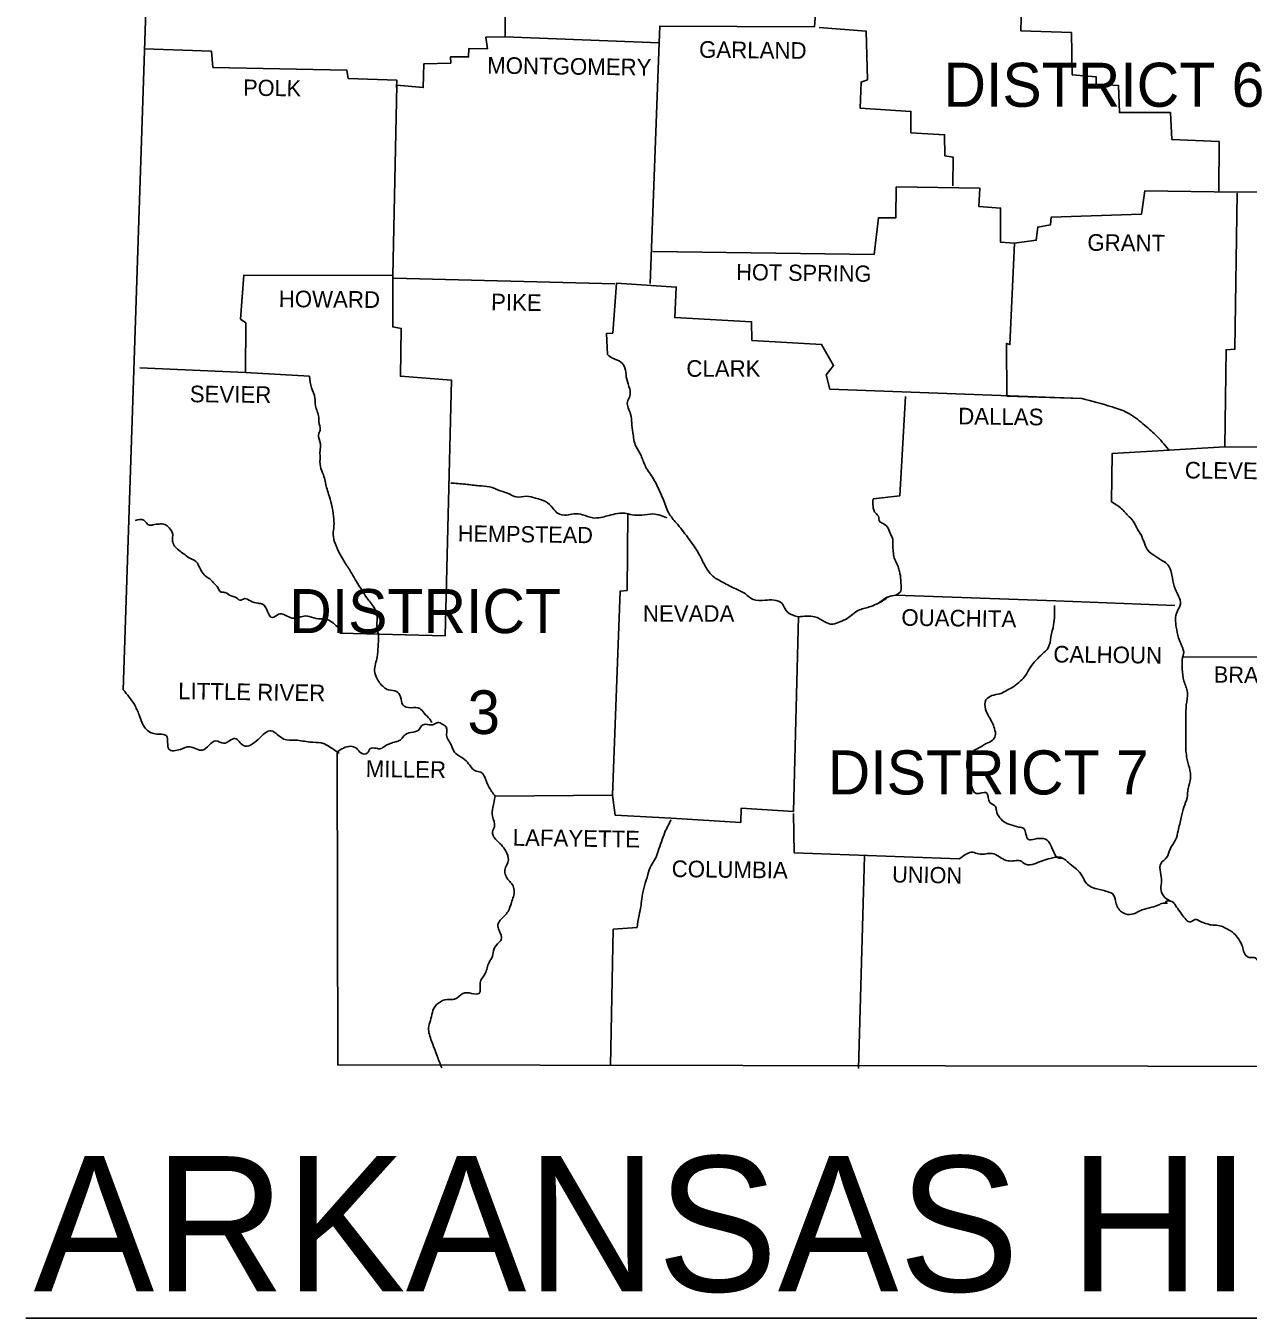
# Model space of a CAD drawing. Extents: x -33639 to 34530, y -17264 to 5867.
# Drawn here: x 1258 to 2998, y 2539 to 4379 of the extents above; entities that cross this region are included whole.
import ezdxf

# ---------------------------------------------------------------- set-up
doc = ezdxf.new("R2010")
doc.units = 0
for name, color, linetype in [('1', 7, 'Continuous'), ('2', 7, 'Continuous'), ('3', 7, 'Continuous'), ('S_MISC_BOUNDARY', 7, 'Continuous')]:
    doc.layers.add(name, color=color, linetype=linetype)

msp = doc.modelspace()

# ---------------------------------------------------------------- linework, layer by layer
at = {"layer": '1'}
msp.add_line((1258, 2539.3), (4771.1, 2539.3), dxfattribs=at)
for points in [[(1332.2, 5841.4), (1446.1, 4926.7), (1396.6, 3433.6)], [(1941.4, 4685.1), (1940.3, 4363.2), (1912.8, 4362.6), (1915, 4346.1), (1888.6, 4346.7), (1888, 4334.6), (1862.2, 4334.6), (1862.7, 4325.8), (1824.2, 4324.7), (1823.6, 4291.1), (1786.2, 4294.4), (1780.2, 4023.6), (1568.3, 4024.2), (1563.3, 3961.4), (1571, 3955.9), (1570.5, 3885.5), (1420.2, 3892.1)], [(2565.5, 4443), (2385.5, 4448.5), (2380.6, 4377.5), (2160.4, 4378.6), (2159.3, 4354.9)], [(2614.5, 4444.6), (2676.1, 4440.8), (2673.9, 4372), (2746, 4369.2), (2747.1, 4309.2), (2781.2, 4306.5), (2781.2, 4296), (2813.2, 4293.8), (2814.3, 4255.3), (2886.9, 4255.3), (2889.1, 4217.3), (2956.3, 4214), (2955.7, 4142.5)], [(2159.3, 4354.9), (1940.3, 4363.2)], [(2387.2, 4376.4), (2453.8, 4371.4), (2456, 4302.1), (2446.6, 4298.8), (2445.5, 4261.9), (2517.6, 4257), (2517.6, 4226.7), (2565.5, 4223.9), (2566.1, 4193.7), (2577.6, 4192), (2577.1, 4151.3)], [(1426.8, 4346.1), (1522, 4342.8), (1524.2, 4319.7), (1714.7, 4315.8), (1716.9, 4303.7), (1786.2, 4301.5), (1785.7, 4291.1)], [(2159.3, 4354.9), (2146.7, 4012.1)], [(2150.5, 4057.7), (2465.3, 4053.3), (2471.4, 4105.6), (2496.2, 4105.6), (2496.7, 4149.6), (2615.6, 4148), (2614.5, 4121.6), (2645.3, 4119.4), (2645.3, 4070.9), (2665.1, 4069.3)], [(2982.1, 4140.8), (2978.8, 3918.5), (2966.2, 3917.9), (2964.5, 3779.8)], [(1780.2, 4023.6), (1780.2, 3950.4), (1792.3, 3948.2), (1791.2, 3880), (1863.8, 3874.5), (1855, 3510.7), (1705.3, 3514.5)], [(1781.3, 4019.8), (2096.1, 4011.5)], [(2085.6, 3910.8), (2084.5, 3941.1), (2093.3, 3941.6), (2098.8, 4012.6), (2183.6, 4007.1), (2181.4, 3963.6), (2290.9, 3957.6), (2291.4, 3931.2), (2390.5, 3925.1), (2407.6, 3895.4), (2397.1, 3882.2), (2402.1, 3861.8), (2760.9, 3848.6)], [(1570.5, 3885.5), (1661.8, 3880)], [(2509.9, 3851.4), (2501.7, 3709.9), (2463.7, 3705.5)], [(2885.3, 3774.9), (2803.8, 3769.9), (2803.3, 3701.1)], [(2114.8, 3684.6), (2113.7, 3575.1), (2103.8, 3574), (2092.8, 3283.9)], [(2496.2, 3568.5), (2724, 3560.2), (2893, 3553.6)], [(2357.5, 3537.6), (2350.3, 3260.3), (2276, 3265.2), (2275.5, 3244.9), (2176.4, 3250.9)], [(2904, 3480.4), (3152.7, 3481)], [(1700.9, 3345), (1702, 2899.8), (3719, 2896.5)], [(2176.4, 3250.9), (2096.6, 3255.3), (2092.8, 3283.9), (1926, 3282.3)], [(2586.4, 3193.1), (2351.4, 3201.9), (2350.3, 3257.5)], [(2451.6, 3197), (2442.8, 2894.8)], [(2128, 3095.2), (2093.9, 3093), (2090, 2899.2)]]:
    msp.add_lwpolyline(points, dxfattribs=at)
for points in [[(2085.6, 3910.8), (2094.4, 3905.3), (2104.9, 3900.3), (2110.4, 3892.1), (2112.6, 3879.4), (2116.4, 3865.7), (2117.5, 3851.4), (2114.2, 3843.6), (2118.6, 3826), (2120.3, 3813.9), (2121.9, 3799.6), (2126.3, 3780.4), (2133.5, 3767.1), (2140.1, 3751.2), (2151.1, 3734.1), (2160.4, 3715.4), (2164.8, 3705.5), (2173.1, 3685.1), (2183.6, 3671.4), (2200.1, 3650.5), (2214.9, 3629), (2223.2, 3613), (2235.8, 3595.4), (2250.2, 3586.6), (2268.3, 3577.3), (2279.9, 3571.8), (2293.1, 3562.4), (2310.1, 3561.3), (2322.8, 3561.3), (2334.4, 3556.4), (2339.9, 3546.5), (2349.8, 3539.9), (2357.5, 3537.6)], [(1661.8, 3880), (1664.6, 3863.5), (1669.5, 3849.1), (1670.1, 3838.1), (1675, 3821.6), (1675, 3815.6), (1676.7, 3803.5), (1674.5, 3796.9), (1677.2, 3783.7), (1676.7, 3773.8), (1676.7, 3765.5), (1677.2, 3751.7), (1681.6, 3739.6), (1686, 3721.5), (1688.8, 3712.1), (1693.2, 3697.8), (1695.9, 3680.2), (1696.5, 3667), (1695.4, 3654.9), (1698.7, 3641.1), (1704.8, 3627.4), (1712.5, 3614.1), (1721.8, 3599.3), (1728.4, 3587.7), (1736.7, 3575.1), (1743.3, 3564.6), (1753.2, 3551.4), (1757.6, 3540.4), (1757.6, 3525), (1759.8, 3510.7), (1759.2, 3494.7), (1758.1, 3480.4), (1754.3, 3460.6), (1757, 3451.2), (1767.5, 3437.5), (1774.1, 3433.6), (1785.7, 3431.4), (1791.2, 3423.7), (1794.5, 3412.2), (1806, 3408.3), (1818.7, 3407.2), (1824.7, 3400.6), (1833, 3391.8), (1835.7, 3387.4)], [(1862.7, 3728.1), (1883.6, 3726.4), (1902.9, 3724.2), (1917.7, 3722.6), (1933.2, 3717.1), (1946.9, 3712.1), (1955.7, 3708.3), (1970.6, 3709.4), (1983.2, 3706.6), (1997.5, 3701.7), (2008, 3692.3), (2014.6, 3685.1), (2027.3, 3682.4), (2037.7, 3684), (2050.4, 3682.9), (2064.7, 3678.5), (2076.2, 3679.1), (2085.6, 3681.3), (2096.6, 3684), (2110.4, 3685.1), (2120.8, 3682.9), (2134.6, 3682.4), (2150.5, 3684), (2170.4, 3678.5)], [(2463.7, 3705.5), (2463.7, 3695), (2467.5, 3685.1), (2471.4, 3680.7), (2473, 3673.6), (2478, 3670.3), (2485.2, 3663.7), (2489, 3654.3), (2491.8, 3648.3), (2491.8, 3640.6), (2492.3, 3632.9), (2493.4, 3623.5), (2500, 3607), (2501.7, 3600.4), (2502.8, 3594.9), (2503.3, 3585.5), (2503.3, 3574.5), (2496.2, 3568.5)], [(2803.3, 3701.1), (2815.9, 3692.8), (2826.4, 3681.8), (2834.1, 3673.6), (2839, 3664.2), (2845.6, 3653.2), (2855, 3632.3), (2863.2, 3625.2), (2874.8, 3618), (2882, 3613), (2889.1, 3597.1), (2892.4, 3581.1), (2898.5, 3566.8), (2901.2, 3555.8), (2896.3, 3544.8), (2895.2, 3522.8), (2898.5, 3507.9), (2902.9, 3496.9), (2905.6, 3484.3), (2904, 3480.4)], [(1413.6, 3674.7), (1425.7, 3675.2), (1434, 3668.1), (1438.9, 3668.6), (1447.7, 3669.7), (1456, 3669.2), (1462, 3664.2), (1467, 3655.4), (1466.5, 3647.2), (1467, 3643.9), (1470.9, 3636.7), (1477.5, 3631.2), (1484.6, 3625.7), (1491.2, 3621.3), (1502.2, 3614.1), (1503.3, 3611.9), (1507.7, 3603.1), (1513.2, 3596), (1519.8, 3591.6), (1527, 3583.9), (1530.3, 3580.6), (1535.8, 3572.9), (1541.8, 3572.3), (1550.1, 3567.4), (1556.2, 3565.7), (1562.8, 3561.3), (1569.4, 3563.5), (1577.6, 3560.2), (1588.6, 3556.9), (1594.7, 3555.8), (1601.8, 3545.4), (1609, 3536.5), (1617.8, 3541.5), (1634.3, 3536.5), (1644.8, 3536), (1654.1, 3538.7), (1661.3, 3538.2), (1674.5, 3534.9), (1682.7, 3534.9), (1691.5, 3531.6), (1699.8, 3525), (1705.3, 3517.8), (1705.3, 3514.5)], [(2485.7, 3566.3), (2471.4, 3556.9), (2460.4, 3552.5), (2452.1, 3549.8), (2444.4, 3547.6), (2434.5, 3541), (2426.8, 3535.4), (2416.4, 3530.5), (2406.5, 3527.2), (2394.3, 3531), (2387.7, 3534.9), (2380.6, 3537.6), (2357.5, 3537.6)], [(2471.4, 3556.9), (2485.7, 3566.3), (2496.2, 3568.5)], [(2721.8, 3553.6), (2720.7, 3526.1), (2716.9, 3509), (2713, 3493.6), (2704.7, 3484.8), (2695.9, 3476), (2687.7, 3466.1), (2680.5, 3454), (2673.4, 3446.3), (2664, 3438.6), (2654.7, 3433.1), (2644.2, 3428.1), (2632.7, 3425.4), (2624.4, 3419.3), (2623.8, 3406.1), (2633.2, 3387.4), (2636.5, 3378.6), (2637.6, 3368.1), (2633.8, 3362.1), (2624.9, 3357.1), (2614.5, 3351.1), (2605.1, 3345.6), (2598.5, 3336.2), (2597.4, 3323.6), (2601.8, 3308.7), (2603.5, 3299.9), (2610.6, 3286.1), (2616.1, 3286.7), (2626, 3286.1), (2627.1, 3283.4), (2627.7, 3280.6), (2629.9, 3273.5), (2638.2, 3267.4), (2639.3, 3261.9), (2644.2, 3251.5), (2652.5, 3244.3), (2658.5, 3242.1), (2671.2, 3238.3), (2677.8, 3236.6), (2684.9, 3220.6), (2693.7, 3221.2), (2700.3, 3222.3), (2711.4, 3219.5), (2716.3, 3212.9), (2721.3, 3201.9), (2727.9, 3194.2), (2732.3, 3194.2)], [(2904, 3480.4), (2906.2, 3446.3), (2911.1, 3429.8), (2909.5, 3412.2), (2908.9, 3395.1), (2908.9, 3379.7), (2908.9, 3364.8), (2908.9, 3349.4), (2910, 3338.4), (2913.9, 3322.5), (2915.5, 3307.6), (2912.2, 3293.3), (2910.6, 3280.1), (2906.2, 3266.9), (2902.3, 3252), (2897.9, 3232.8), (2894.1, 3220.1), (2886.4, 3206.9), (2881.4, 3194.8), (2873.7, 3187.1), (2872.6, 3173.9), (2874.3, 3161.8), (2873.2, 3150.7), (2877, 3140.3), (2886.9, 3133.1)], [(1396.6, 3433.6), (1412.5, 3412.7), (1419.1, 3397.9), (1428.5, 3378.6), (1442.2, 3370.9), (1458.2, 3368.1), (1461.5, 3349.4), (1478, 3348.9), (1491.2, 3352.7), (1509.4, 3347.8), (1528.6, 3361), (1539.6, 3357.7), (1555.6, 3364.3), (1567.7, 3354.4), (1588.6, 3363.2), (1607.3, 3375.3), (1625, 3363.7), (1642, 3362.1), (1662.4, 3359.3), (1678.3, 3358.2), (1692.6, 3351.1), (1703.1, 3343.9), (1700.9, 3345)], [(1700.9, 3345), (1720.2, 3353.3), (1728.4, 3350.5), (1735.6, 3343.4), (1743.8, 3343.4), (1748.2, 3350), (1756.5, 3350.5), (1763.1, 3350), (1770.2, 3354.4), (1776.3, 3357.1), (1784.6, 3359.9), (1790.6, 3362.1), (1796.1, 3368.1), (1806, 3373.1), (1817.6, 3376.9), (1820.9, 3382.4), (1826.4, 3384.7), (1837.4, 3384.1), (1844.5, 3387.4), (1850.6, 3384.7), (1856.1, 3380.8), (1857.2, 3366.5), (1861.6, 3358.8), (1868.2, 3345), (1877.6, 3337.9), (1886.4, 3330.7), (1889.7, 3326.3), (1899, 3318.1), (1907.3, 3315.3), (1911.1, 3309.3), (1917.2, 3294.9), (1926, 3282.3)], [(1926, 3282.3), (1922.7, 3266.3), (1922.1, 3253.7), (1924.9, 3238.8), (1922.1, 3231.7), (1926.5, 3221.2), (1934.8, 3212.9), (1940.9, 3204.1), (1944.7, 3191.5), (1939.8, 3177.2), (1945.3, 3162.3), (1950.2, 3156.8), (1953, 3148), (1949.1, 3130.9), (1944.2, 3118.3), (1933.2, 3105.6), (1929.8, 3099.6), (1931.5, 3091.3), (1934.3, 3078.1), (1931.5, 3074.3), (1924.3, 3064.9), (1922.1, 3054.4), (1917.2, 3045.6), (1911.7, 3029.7), (1904.5, 3016.5), (1903.4, 3001.6), (1892.4, 3001.6), (1879.8, 3001.6), (1868.2, 2993.3), (1857.8, 2992.8), (1845.1, 2987.8), (1837.4, 2977.4), (1834.6, 2965.8), (1831.3, 2954.8), (1834.6, 2936.1), (1839.6, 2922.9), (1843.4, 2912.4), (1850, 2895.4)], [(2128, 3095.2), (2130.7, 3112.8), (2133.5, 3126.5), (2135.1, 3139.7), (2138.4, 3154.6), (2143.4, 3170.6), (2147.8, 3183.8), (2153.8, 3193.1), (2157.7, 3204.1), (2162.6, 3217.3), (2167.6, 3231.1), (2176.4, 3248.7)], [(2586.4, 3193.1), (2595.2, 3199.2), (2603.5, 3202.5), (2611.7, 3200.8), (2620.5, 3199.7), (2628.2, 3200.8), (2638.2, 3199.2), (2646.4, 3194.2), (2655.8, 3190.4), (2665.1, 3190.4), (2673.4, 3190.4), (2680.5, 3185.4), (2693.7, 3186), (2704.7, 3190.4), (2715.8, 3193.7), (2730.6, 3195.3), (2743.8, 3186), (2753.2, 3178.3), (2760.9, 3169.5), (2766.4, 3159.6), (2772.4, 3154.1), (2782.3, 3150.2), (2790.1, 3148.5), (2799.4, 3145.8), (2804.4, 3143.6), (2808.8, 3133.1), (2815.9, 3118.8), (2829.7, 3113.9), (2846.7, 3120.5), (2860.5, 3124.3), (2870.4, 3127.6), (2876.5, 3129.8), (2882, 3130.4), (2880.3, 3131.5), (2886.9, 3133.1), (2893, 3128.7), (2896.8, 3122.7), (2903.4, 3113.9), (2909.5, 3106.2), (2915.5, 3103.4), (2921.6, 3106.7), (2929.8, 3104), (2937, 3101.2), (2945.3, 3099), (2952.4, 3098.5), (2961.8, 3096.3), (2968.9, 3092.4), (2975.5, 3088.6), (2982.1, 3081.4), (2988.7, 3070.4), (2990.9, 3061.6), (2998.6, 3052.8), (3005.8, 3052.8), (3016.2, 3038.5), (3020.1, 3033), (3028.4, 3023.1), (3034.4, 3023.1), (3046, 3020.9)]]:
    msp.add_spline(points, degree=3, dxfattribs=at)
at = {"layer": 'S_MISC_BOUNDARY'}
msp.add_line((2884.2, 3776), (2884.2, 3774.9), dxfattribs=at)
for points in [[(2654.1, 3851.9), (2653.6, 3926.7), (2658.5, 3925.1), (2665.1, 4069.3), (2695.9, 4073.7), (2698.1, 4092.4), (2716.3, 4095.7), (2717.4, 4106.7), (2845.6, 4110.6), (2850.6, 4144.1), (2982.1, 4141.9), (3403.1, 4143.6), (3404.2, 4211.3), (3612.3, 4205.8)], [(3612.3, 4205.8), (3404.2, 4211.3), (3403.1, 4143.6), (2982.1, 4141.9), (2850.6, 4144.1), (2845.6, 4110.6), (2717.4, 4106.7), (2716.3, 4095.7), (2698.1, 4092.4), (2695.9, 4073.7), (2665.1, 4069.3), (2658.5, 3925.1), (2653.6, 3926.7), (2654.1, 3851.9), (2760.9, 3848.6)], [(3135.1, 3320.3), (3147.2, 3328), (3152.7, 3481), (3149.4, 3709.4), (3161, 3709.9), (3160.4, 3778.7), (3159.3, 3778.7), (2964.5, 3779.8), (2884.2, 3774.9)], [(2884.2, 3774.9), (2964.5, 3779.8), (3159.3, 3778.7), (3160.4, 3778.7), (3161, 3709.9), (3149.4, 3709.4), (3152.7, 3481), (3147.2, 3328), (3135.1, 3320.3)]]:
    msp.add_lwpolyline(points, dxfattribs=at)
for points in [[(2884.2, 3776), (2866, 3796.3), (2847.8, 3812.3), (2825.8, 3828.2), (2803.8, 3836.5), (2760.9, 3848.6)], [(2760.9, 3848.6), (2803.8, 3836.5), (2825.8, 3828.2), (2847.8, 3812.3), (2866, 3796.3), (2884.2, 3776)]]:
    msp.add_spline(points, degree=3, dxfattribs=at)

# ---------------------------------------------------------------- texts
at = {"layer": '2'}
for s, height, rotation, p in [('GARLAND', 23.67, 359.3658, (2216, 4333.5)), ('MONTGOMERY', 23.67, 359.2944, (1914.4, 4310.9)), ('POLK', 23.11, 359.2152, (1567.2, 4279.5)), ('GRANT', 23.67, 359.4032, (2768.6, 4058.8)), ('HOT SPRING', 23.11, 359.2216, (2268.9, 4017)), ('HOWARD', 23.67, 359.5145, (1617.8, 3978.5)), ('PIKE', 23.66, 359.0452, (1919.9, 3974.1)), ('SEVIER', 23.67, 359.4271, (1491.2, 3843.1)), ('DALLAS', 23.66, 359.2462, (2584.8, 3811.7)), ('CLEVELAND', 23.67, 359.3377, (2907.3, 3734.7)), ('HEMPSTEAD', 23.11, 359.1885, (1872.6, 3645)), ('OUACHITA', 23.67, 359.2043, (2503.9, 3525)), ('CALHOUN', 23.67, 359.3634, (2720.2, 3472.7)), ('BRADLEY', 23.11, 359.1449, (2948.6, 3444.1)), ('LITTLE RIVER', 23.666, 359.1697, (1474.7, 3420.4)), ('MILLER', 23.66, 359.1319, (1741.6, 3309.8)), ('LAFAYETTE', 23.66, 359.1839, (1950.8, 3211.8)), ('COLUMBIA', 23.66, 359.2125, (2177, 3167.3)), ('UNION', 23.11, 358.9584, (2490.7, 3159.6))]:
    msp.add_text(s, height=height, rotation=rotation, dxfattribs=at).set_placement(p)
for s, height, p in [('CLARK', 23.67, (2198, 3879.3)), ('NEVADA', 23.67, (2136.2, 3530.5)), ('ARKANSAS HIGHWAY DISTRICT 2', 192.623, (1269, 2577.3))]:
    msp.add_text(s, height=height, dxfattribs=at).set_placement(p)
at = {"layer": '3'}
for s, height, p in [('DISTRICT 6', 62.74, (2563.9, 4263.6)), ('DISTRICT', 62.74, (1632.8, 3514.4)), ('3', 62.2, (1886.6, 3370.8)), ('DISTRICT 7', 62.74, (2399.2, 3284.8))]:
    msp.add_text(s, height=height, dxfattribs=at).set_placement(p)

doc.saveas('drawing.dxf')
